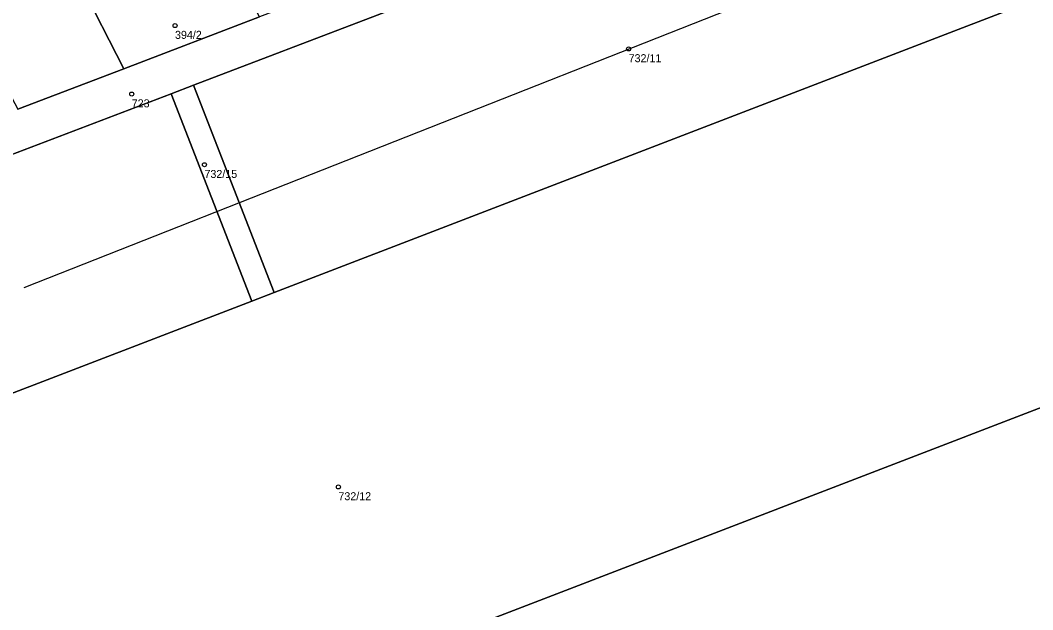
# Model space of a CAD drawing. Extents: x -550098 to -546083, y -1127254 to -1124489.
# Drawn here: x -547582.1 to -547455.5, y -1126096.8 to -1126023.1 of the extents above; entities that cross this region are included whole.
import ezdxf

# ---------------------------------------------------------------- set-up
doc = ezdxf.new("R2010")
doc.units = 0
for name, color, linetype in [('Definiční body', 7, 'Continuous'), ('Polygon parcely', 7, 'Continuous'), ('Vrstva 14', 7, 'Continuous')]:
    doc.layers.add(name, color=color, linetype=linetype)

msp = doc.modelspace()

# ---------------------------------------------------------------- linework, layer by layer
at = {"layer": 'Definiční body'}
for centre in [(-547562.73, -1126023.76994), (-547506.04, -1126026.68994), (-547568.14, -1126032.32994), (-547559.05, -1126041.15994), (-547542.31, -1126081.44994)]:
    msp.add_circle(centre, 0.25, dxfattribs=at)
at = {"layer": 'Polygon parcely'}
msp.add_lwpolyline([(-547659.47, -1126068.98), (-547563.23, -1126032.28), (-547560.42, -1126031.21), (-547468.62, -1125996.19), (-547460.29, -1125999.28), (-547467.9, -1125984.07), (-547469.46, -1125988.07), (-547469.88, -1125989.15), (-547470.85, -1125991.64), (-547479.22, -1125994.83), (-547486.05, -1125997.44), (-547492.87, -1126000.04), (-547500.67, -1126003.02), (-547502.12, -1126003.57), (-547511.18, -1126007.03), (-547520.24, -1126010.49), (-547529.49, -1126014.03), (-547536.31, -1126016.63), (-547538.06, -1126017.3), (-547543.13, -1126019.23), (-547552.16, -1126022.68), (-547569.13, -1126029.16), (-547582.39, -1126034.23)], dxfattribs=at)
for points in [[(-547450.43, -1126018.67), (-547460.29, -1125999.28), (-547468.62, -1125996.19), (-547560.42, -1126031.21), (-547550.34, -1126057.12)], [(-547582.39, -1126034.23), (-547569.13, -1126029.16), (-547580.06, -1126007.78), (-547580.98, -1126005.99), (-547585.22, -1125997.68), (-547599.18, -1126002.51)], [(-547569.13, -1126029.16), (-547552.16, -1126022.68), (-547553.11, -1126020.83), (-547563.09, -1126001.32), (-547564.01, -1125999.53), (-547580.98, -1126005.99), (-547580.06, -1126007.78)], [(-547428.63, -1126061.55), (-547450.43, -1126018.67), (-547550.34, -1126057.12), (-547553.14, -1126058.2), (-547653.1, -1126096.66), (-547640.65, -1126143.15)], [(-547560.42, -1126031.21), (-547563.23, -1126032.28), (-547553.14, -1126058.2), (-547550.34, -1126057.12)], [(-547553.14, -1126058.2), (-547563.23, -1126032.28), (-547659.47, -1126068.98), (-547660.15, -1126070.29), (-547653.1, -1126096.66)], [(-547366.68, -1126193.82), (-547367.62, -1126184.46), (-547368.07, -1126180.05), (-547372.39, -1126172.17), (-547428.63, -1126061.55), (-547640.65, -1126143.15), (-547617.21, -1126230.73), (-547596.99, -1126306.2), (-547596.77, -1126310.15), (-547597.69, -1126313.31), (-547599.52, -1126316), (-547595.4, -1126331.36), (-547351.7, -1126237.97), (-547355.19, -1126223.25), (-547359.69, -1126209.67)]]:
    msp.add_lwpolyline(points, close=True, dxfattribs=at)
at = {"layer": 'Vrstva 14'}
msp.add_lwpolyline([(-547581.58552, -1126056.49838), (-547492.00768, -1126021.16859), (-547479.13026, -1126017.7769), (-547457.43708, -1126006.56027), (-547449.38263, -1126001.78138), (-547442.07327, -1125996.65867), (-547436.03688, -1125991.55509), (-547377.89727, -1125950.91581), (-547338.28835, -1125928.11607), (-547317.74261, -1125915.26345)], dxfattribs=at)

# ---------------------------------------------------------------- texts
at = {"layer": 'Definiční body'}
for s, p in [('394/2', (-547562.73, -1126025.426)), ('732/11', (-547506.04, -1126028.346)), ('723', (-547568.14, -1126033.986)), ('732/15', (-547559.05, -1126042.816)), ('732/12', (-547542.31, -1126083.106))]:
    msp.add_text(s, height=0.999996, dxfattribs=at).set_placement(p)

doc.saveas('drawing.dxf')
